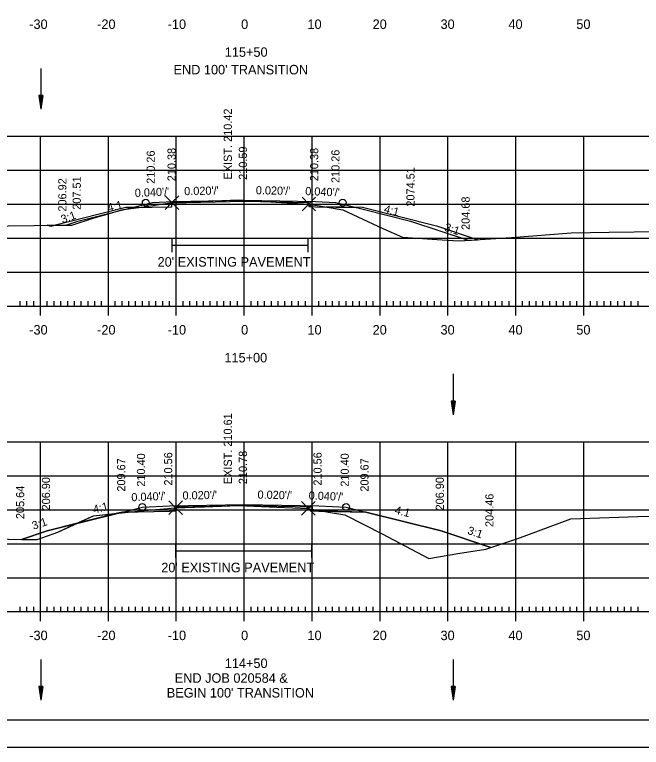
# Model space of a CAD drawing. Extents: x 1312042 to 1371461, y 379929 to 1834241.
# Drawn here: x 1371264.5 to 1371356.8, y 380142.3 to 380250.2 of the extents above; entities that cross this region are included whole.
import ezdxf

# ---------------------------------------------------------------- set-up
doc = ezdxf.new("R2010")
doc.units = 0
for name, color, linetype in [('Default', 7, 'Continuous'), ('R_Alt Surface', 7, 'Continuous'), ('R_Axis', 7, 'Continuous'), ('R_Axis Annot', 7, 'Continuous'), ('R_Border', 7, 'Continuous'), ('R_Exist Surface', 7, 'Continuous'), ('R_Fin Surface', 7, 'Continuous'), ('R_Grid', 7, 'Continuous'), ('R_No Plot', 7, 'Continuous'), ('R_Water Annot', 7, 'Continuous'), ('R_Xsect Elev', 7, 'Continuous'), ('R_Xsect Slope', 7, 'Continuous')]:
    doc.layers.add(name, color=color, linetype=linetype)

msp = doc.modelspace()

# ---------------------------------------------------------------- linework, layer by layer
at = {"layer": 'Default'}
for p, q in [((1371287.64, 380217.25), (1371287.64, 380215.19)), ((1371307.64, 380217.25), (1371307.64, 380215.19)), ((1371287.64, 380216.22), (1371307.64, 380216.22)), ((1371307.72, 380177.67), (1371308.28, 380177.66)), ((1371288.18, 380172.25), (1371288.18, 380170.19)), ((1371308.18, 380172.25), (1371308.18, 380170.19)), ((1371288.18, 380171.22), (1371308.18, 380171.22))]:
    msp.add_line(p, q, dxfattribs=at)
at = {"layer": 'R_Alt Surface'}
for points in [[(1371281.78, 380221.76), (1371287.64, 380221.88), (1371287.64, 380222.46), (1371298.28, 380222.67), (1371307.8, 380222.48), (1371307.8, 380221.9), (1371308.79, 380221.88), (1371314.78, 380221.76)], [(1371280.36, 380176.92), (1371287.29, 380177.06), (1371288.18, 380177.08), (1371288.18, 380177.66), (1371298.28, 380177.86), (1371308.28, 380177.66), (1371308.28, 380177.08), (1371309.29, 380177.06), (1371316.19, 380176.92)]]:
    msp.add_lwpolyline(points, dxfattribs=at)
at = {"layer": 'R_Axis'}
for p, q in [((1371265.28, 380207.25), (1371265.28, 380207.95)), ((1371266.28, 380207.25), (1371266.28, 380207.95)), ((1371267.28, 380207.25), (1371267.28, 380207.95)), ((1371268.28, 380205.85), (1371268.28, 380208.65)), ((1371269.28, 380207.25), (1371269.28, 380207.95)), ((1371270.28, 380207.25), (1371270.28, 380207.95)), ((1371271.28, 380207.25), (1371271.28, 380207.95)), ((1371272.28, 380207.25), (1371272.28, 380207.95)), ((1371273.28, 380207.25), (1371273.28, 380207.95)), ((1371274.28, 380207.25), (1371274.28, 380207.95)), ((1371275.28, 380207.25), (1371275.28, 380207.95)), ((1371276.28, 380207.25), (1371276.28, 380207.95)), ((1371277.28, 380207.25), (1371277.28, 380207.95)), ((1371278.28, 380205.85), (1371278.28, 380208.65)), ((1371279.28, 380207.25), (1371279.28, 380207.95)), ((1371280.28, 380207.25), (1371280.28, 380207.95)), ((1371281.28, 380207.25), (1371281.28, 380207.95)), ((1371282.28, 380207.25), (1371282.28, 380207.95)), ((1371283.28, 380207.25), (1371283.28, 380207.95)), ((1371284.28, 380207.25), (1371284.28, 380207.95)), ((1371285.28, 380207.25), (1371285.28, 380207.95)), ((1371286.28, 380207.25), (1371286.28, 380207.95)), ((1371287.28, 380207.25), (1371287.28, 380207.95)), ((1371288.28, 380205.85), (1371288.28, 380208.65)), ((1371289.28, 380207.25), (1371289.28, 380207.95)), ((1371290.28, 380207.25), (1371290.28, 380207.95)), ((1371291.28, 380207.25), (1371291.28, 380207.95)), ((1371292.28, 380207.25), (1371292.28, 380207.95)), ((1371293.28, 380207.25), (1371293.28, 380207.95)), ((1371294.28, 380207.25), (1371294.28, 380207.95)), ((1371295.28, 380207.25), (1371295.28, 380207.95)), ((1371296.28, 380207.25), (1371296.28, 380207.95)), ((1371297.28, 380207.25), (1371297.28, 380207.95)), ((1371298.28, 380205.85), (1371298.28, 380208.65)), ((1371299.28, 380207.25), (1371299.28, 380207.95)), ((1371300.28, 380207.25), (1371300.28, 380207.95)), ((1371301.28, 380207.25), (1371301.28, 380207.95)), ((1371302.28, 380207.25), (1371302.28, 380207.95)), ((1371303.28, 380207.25), (1371303.28, 380207.95)), ((1371304.28, 380207.25), (1371304.28, 380207.95)), ((1371305.28, 380207.25), (1371305.28, 380207.95)), ((1371306.28, 380207.25), (1371306.28, 380207.95)), ((1371307.28, 380207.25), (1371307.28, 380207.95)), ((1371308.28, 380205.85), (1371308.28, 380208.65)), ((1371309.28, 380207.25), (1371309.28, 380207.95)), ((1371310.28, 380207.25), (1371310.28, 380207.95)), ((1371311.28, 380207.25), (1371311.28, 380207.95)), ((1371312.28, 380207.25), (1371312.28, 380207.95)), ((1371313.28, 380207.25), (1371313.28, 380207.95)), ((1371314.28, 380207.25), (1371314.28, 380207.95)), ((1371315.28, 380207.25), (1371315.28, 380207.95)), ((1371316.28, 380207.25), (1371316.28, 380207.95)), ((1371317.28, 380207.25), (1371317.28, 380207.95)), ((1371318.28, 380205.85), (1371318.28, 380208.65)), ((1371319.28, 380207.25), (1371319.28, 380207.95)), ((1371320.28, 380207.25), (1371320.28, 380207.95)), ((1371321.28, 380207.25), (1371321.28, 380207.95)), ((1371322.28, 380207.25), (1371322.28, 380207.95)), ((1371323.28, 380207.25), (1371323.28, 380207.95)), ((1371324.28, 380207.25), (1371324.28, 380207.95)), ((1371325.28, 380207.25), (1371325.28, 380207.95)), ((1371326.28, 380207.25), (1371326.28, 380207.95)), ((1371327.28, 380207.25), (1371327.28, 380207.95)), ((1371328.28, 380205.85), (1371328.28, 380208.65)), ((1371329.28, 380207.25), (1371329.28, 380207.95)), ((1371330.28, 380207.25), (1371330.28, 380207.95)), ((1371331.28, 380207.25), (1371331.28, 380207.95)), ((1371332.28, 380207.25), (1371332.28, 380207.95)), ((1371333.28, 380207.25), (1371333.28, 380207.95)), ((1371334.28, 380207.25), (1371334.28, 380207.95)), ((1371335.28, 380207.25), (1371335.28, 380207.95)), ((1371336.28, 380207.25), (1371336.28, 380207.95)), ((1371337.28, 380207.25), (1371337.28, 380207.95)), ((1371338.28, 380205.85), (1371338.28, 380208.65)), ((1371339.28, 380207.25), (1371339.28, 380207.95)), ((1371340.28, 380207.25), (1371340.28, 380207.95)), ((1371341.28, 380207.25), (1371341.28, 380207.95)), ((1371342.28, 380207.25), (1371342.28, 380207.95)), ((1371343.28, 380207.25), (1371343.28, 380207.95)), ((1371344.28, 380207.25), (1371344.28, 380207.95)), ((1371345.28, 380207.25), (1371345.28, 380207.95)), ((1371346.28, 380207.25), (1371346.28, 380207.95)), ((1371347.28, 380207.25), (1371347.28, 380207.95)), ((1371348.28, 380205.85), (1371348.28, 380208.65)), ((1371349.28, 380207.25), (1371349.28, 380207.95)), ((1371350.28, 380207.25), (1371350.28, 380207.95)), ((1371351.28, 380207.25), (1371351.28, 380207.95)), ((1371352.28, 380207.25), (1371352.28, 380207.95)), ((1371353.28, 380207.25), (1371353.28, 380207.95)), ((1371354.28, 380207.25), (1371354.28, 380207.95)), ((1371355.28, 380207.25), (1371355.28, 380207.95)), ((1371356.28, 380207.25), (1371356.28, 380207.95)), ((1371158.28, 380207.25), (1371438.28, 380207.25)), ((1371268.28, 380160.85), (1371268.28, 380163.65)), ((1371278.28, 380160.85), (1371278.28, 380163.65)), ((1371288.28, 380160.85), (1371288.28, 380163.65)), ((1371298.28, 380160.85), (1371298.28, 380163.65)), ((1371308.28, 380160.85), (1371308.28, 380163.65)), ((1371318.28, 380160.85), (1371318.28, 380163.65)), ((1371328.28, 380160.85), (1371328.28, 380163.65)), ((1371338.28, 380160.85), (1371338.28, 380163.65)), ((1371348.28, 380160.85), (1371348.28, 380163.65)), ((1371265.28, 380162.25), (1371265.28, 380162.95)), ((1371266.28, 380162.25), (1371266.28, 380162.95)), ((1371267.28, 380162.25), (1371267.28, 380162.95)), ((1371269.28, 380162.25), (1371269.28, 380162.95)), ((1371270.28, 380162.25), (1371270.28, 380162.95)), ((1371271.28, 380162.25), (1371271.28, 380162.95)), ((1371272.28, 380162.25), (1371272.28, 380162.95)), ((1371273.28, 380162.25), (1371273.28, 380162.95)), ((1371274.28, 380162.25), (1371274.28, 380162.95)), ((1371275.28, 380162.25), (1371275.28, 380162.95)), ((1371276.28, 380162.25), (1371276.28, 380162.95)), ((1371277.28, 380162.25), (1371277.28, 380162.95)), ((1371279.28, 380162.25), (1371279.28, 380162.95)), ((1371280.28, 380162.25), (1371280.28, 380162.95)), ((1371281.28, 380162.25), (1371281.28, 380162.95)), ((1371282.28, 380162.25), (1371282.28, 380162.95)), ((1371283.28, 380162.25), (1371283.28, 380162.95)), ((1371284.28, 380162.25), (1371284.28, 380162.95)), ((1371285.28, 380162.25), (1371285.28, 380162.95)), ((1371286.28, 380162.25), (1371286.28, 380162.95)), ((1371287.28, 380162.25), (1371287.28, 380162.95)), ((1371289.28, 380162.25), (1371289.28, 380162.95)), ((1371290.28, 380162.25), (1371290.28, 380162.95)), ((1371291.28, 380162.25), (1371291.28, 380162.95)), ((1371292.28, 380162.25), (1371292.28, 380162.95)), ((1371293.28, 380162.25), (1371293.28, 380162.95)), ((1371294.28, 380162.25), (1371294.28, 380162.95)), ((1371295.28, 380162.25), (1371295.28, 380162.95)), ((1371296.28, 380162.25), (1371296.28, 380162.95)), ((1371297.28, 380162.25), (1371297.28, 380162.95)), ((1371299.28, 380162.25), (1371299.28, 380162.95)), ((1371300.28, 380162.25), (1371300.28, 380162.95)), ((1371301.28, 380162.25), (1371301.28, 380162.95)), ((1371302.28, 380162.25), (1371302.28, 380162.95)), ((1371303.28, 380162.25), (1371303.28, 380162.95)), ((1371304.28, 380162.25), (1371304.28, 380162.95)), ((1371305.28, 380162.25), (1371305.28, 380162.95)), ((1371306.28, 380162.25), (1371306.28, 380162.95)), ((1371307.28, 380162.25), (1371307.28, 380162.95)), ((1371309.28, 380162.25), (1371309.28, 380162.95)), ((1371310.28, 380162.25), (1371310.28, 380162.95)), ((1371311.28, 380162.25), (1371311.28, 380162.95)), ((1371312.28, 380162.25), (1371312.28, 380162.95)), ((1371313.28, 380162.25), (1371313.28, 380162.95)), ((1371314.28, 380162.25), (1371314.28, 380162.95)), ((1371315.28, 380162.25), (1371315.28, 380162.95)), ((1371316.28, 380162.25), (1371316.28, 380162.95)), ((1371317.28, 380162.25), (1371317.28, 380162.95)), ((1371319.28, 380162.25), (1371319.28, 380162.95)), ((1371320.28, 380162.25), (1371320.28, 380162.95)), ((1371321.28, 380162.25), (1371321.28, 380162.95)), ((1371322.28, 380162.25), (1371322.28, 380162.95)), ((1371323.28, 380162.25), (1371323.28, 380162.95)), ((1371324.28, 380162.25), (1371324.28, 380162.95)), ((1371325.28, 380162.25), (1371325.28, 380162.95)), ((1371326.28, 380162.25), (1371326.28, 380162.95)), ((1371327.28, 380162.25), (1371327.28, 380162.95)), ((1371329.28, 380162.25), (1371329.28, 380162.95)), ((1371330.28, 380162.25), (1371330.28, 380162.95)), ((1371331.28, 380162.25), (1371331.28, 380162.95)), ((1371332.28, 380162.25), (1371332.28, 380162.95)), ((1371333.28, 380162.25), (1371333.28, 380162.95)), ((1371334.28, 380162.25), (1371334.28, 380162.95)), ((1371335.28, 380162.25), (1371335.28, 380162.95)), ((1371336.28, 380162.25), (1371336.28, 380162.95)), ((1371337.28, 380162.25), (1371337.28, 380162.95)), ((1371339.28, 380162.25), (1371339.28, 380162.95)), ((1371340.28, 380162.25), (1371340.28, 380162.95)), ((1371341.28, 380162.25), (1371341.28, 380162.95)), ((1371342.28, 380162.25), (1371342.28, 380162.95)), ((1371343.28, 380162.25), (1371343.28, 380162.95)), ((1371344.28, 380162.25), (1371344.28, 380162.95)), ((1371345.28, 380162.25), (1371345.28, 380162.95)), ((1371346.28, 380162.25), (1371346.28, 380162.95)), ((1371347.28, 380162.25), (1371347.28, 380162.95)), ((1371349.28, 380162.25), (1371349.28, 380162.95)), ((1371350.28, 380162.25), (1371350.28, 380162.95)), ((1371351.28, 380162.25), (1371351.28, 380162.95)), ((1371352.28, 380162.25), (1371352.28, 380162.95)), ((1371353.28, 380162.25), (1371353.28, 380162.95)), ((1371354.28, 380162.25), (1371354.28, 380162.95)), ((1371355.28, 380162.25), (1371355.28, 380162.95)), ((1371356.28, 380162.25), (1371356.28, 380162.95)), ((1371158.28, 380162.25), (1371438.28, 380162.25))]:
    msp.add_line(p, q, dxfattribs=at)
at = {"layer": 'R_Border'}
msp.add_line((1371456.46, 380146.25), (1371140.28, 380146.25), dxfattribs=at)
at = {"layer": 'R_Exist Surface'}
for points in [[(1371255.66, 380218.96), (1371267.37, 380219.11), (1371272.89, 380219.18), (1371276.02, 380220.17), (1371280.44, 380221.48), (1371284.24, 380221.97), (1371287.64, 380222.48), (1371292.49, 380222.67), (1371297.49, 380222.87), (1371302.99, 380222.55), (1371307.8, 380222.26), (1371309.92, 380221.93), (1371312.78, 380221.44), (1371318.71, 380218.65), (1371321.6, 380217.4), (1371328.19, 380216.94), (1371329.94, 380216.86), (1371337.65, 380217.32), (1371346.44, 380218.02), (1371352.03, 380218.14), (1371366.76, 380218.33)], [(1371258.75, 380173), (1371265.98, 380172.87), (1371267.8, 380172.89), (1371270.81, 380173.96), (1371276.06, 380176.37), (1371283.52, 380177.13), (1371288.18, 380177.54), (1371292.41, 380177.7), (1371297.44, 380177.88), (1371303.07, 380177.63), (1371307.72, 380177.45), (1371310.98, 380176.87), (1371313.11, 380176.51), (1371318.58, 380173.69), (1371325.49, 380170.08), (1371329.74, 380170.82), (1371333.85, 380171.47), (1371338.57, 380173.02), (1371346.36, 380175.92), (1371356.23, 380176.24), (1371361.36, 380176.42)]]:
    msp.add_lwpolyline(points, dxfattribs=at)
at = {"layer": 'R_Fin Surface'}
for points in [[(1371272, 380219.17), (1371273.78, 380219.76), (1371280.58, 380221.46), (1371284.78, 380222.51), (1371287.78, 380222.63), (1371298.28, 380222.84), (1371308.78, 380222.63), (1371311.78, 380222.51), (1371316, 380221.46), (1371322.78, 380219.76), (1371331.25, 380216.94)], [(1371265.48, 380172.88), (1371269.28, 380174.15), (1371280.36, 380176.92), (1371283.28, 380177.65), (1371287.28, 380177.81), (1371298.28, 380178.03), (1371309.28, 380177.81), (1371313.28, 380177.65), (1371316.19, 380176.92), (1371327.28, 380174.15), (1371334.59, 380171.71)]]:
    msp.add_lwpolyline(points, dxfattribs=at)
at = {"layer": 'R_Grid'}
for p, q in [((1371158.28, 380232.25), (1371438.28, 380232.25)), ((1371268.28, 380207.25), (1371268.28, 380232.25)), ((1371278.28, 380207.25), (1371278.28, 380232.25)), ((1371288.28, 380207.25), (1371288.28, 380232.25)), ((1371298.28, 380207.25), (1371298.28, 380232.25)), ((1371308.28, 380207.25), (1371308.28, 380232.25)), ((1371318.28, 380207.25), (1371318.28, 380232.25)), ((1371328.28, 380207.25), (1371328.28, 380232.25)), ((1371338.28, 380207.25), (1371338.28, 380232.25)), ((1371348.28, 380207.25), (1371348.28, 380232.25)), ((1371158.28, 380227.25), (1371438.28, 380227.25)), ((1371158.28, 380222.25), (1371438.28, 380222.25)), ((1371158.28, 380217.25), (1371438.28, 380217.25)), ((1371158.28, 380212.25), (1371438.28, 380212.25)), ((1371158.28, 380207.25), (1371438.28, 380207.25)), ((1371158.28, 380187.25), (1371438.28, 380187.25)), ((1371268.28, 380162.25), (1371268.28, 380187.25)), ((1371278.28, 380162.25), (1371278.28, 380187.25)), ((1371288.28, 380162.25), (1371288.28, 380187.25)), ((1371298.28, 380162.25), (1371298.28, 380187.25)), ((1371308.28, 380162.25), (1371308.28, 380187.25)), ((1371318.28, 380162.25), (1371318.28, 380187.25)), ((1371328.28, 380162.25), (1371328.28, 380187.25)), ((1371338.28, 380162.25), (1371338.28, 380187.25)), ((1371348.28, 380162.25), (1371348.28, 380187.25)), ((1371158.28, 380182.25), (1371438.28, 380182.25)), ((1371158.28, 380177.25), (1371438.28, 380177.25)), ((1371158.28, 380172.25), (1371438.28, 380172.25)), ((1371158.28, 380167.25), (1371438.28, 380167.25)), ((1371158.28, 380162.25), (1371438.28, 380162.25))]:
    msp.add_line(p, q, dxfattribs=at)
at = {"layer": 'R_No Plot'}
msp.add_line((1371127.88, 380142.27), (1371461.21, 380142.27), dxfattribs=at)
for points in [[(1371127.87, 380355.6), (1371461.21, 380355.6), (1371461.21, 380142.26), (1371127.87, 380142.26)], [(1371374.2, 380351.71), (1371374.2, 380341.83), (1371409.93, 380341.83), (1371409.93, 380338.91), (1371433.13, 380338.91), (1371433.13, 380314.57), (1371456.46, 380314.57), (1371456.46, 380146.25), (1371140.28, 380146.25), (1371140.28, 380351.71)], [(1371270.49, 380219.15), (1371272.89, 380219.18), (1371276.02, 380220.17), (1371280.44, 380221.48), (1371282.75, 380221.78), (1371280.86, 380221.74)], [(1371310.37, 380221.85), (1371312.78, 380221.44), (1371318.71, 380218.65), (1371321.6, 380217.4), (1371328.19, 380216.94), (1371329.94, 380216.86), (1371332.64, 380217.02), (1371326.78, 380218.97), (1371315.69, 380221.74)], [(1371269.28, 380219.14), (1371270.49, 380219.15), (1371269.78, 380218.97)], [(1371273.55, 380175.22), (1371276.06, 380176.37), (1371279.61, 380176.73)], [(1371279.61, 380176.73), (1371281.75, 380176.95), (1371280.36, 380176.92)], [(1371310, 380177.04), (1371310.98, 380176.87), (1371313.11, 380176.51), (1371318.58, 380173.69), (1371325.49, 380170.08), (1371329.74, 380170.82), (1371333.85, 380171.47), (1371334.59, 380171.71), (1371327.28, 380174.15), (1371316.19, 380176.92)], [(1371265.48, 380172.88), (1371265.98, 380172.87), (1371267.8, 380172.89), (1371270.81, 380173.96), (1371273.55, 380175.22), (1371269.28, 380174.15)]]:
    msp.add_lwpolyline(points, close=True, dxfattribs=at)
for points in [[(1371287.64, 380222.48), (1371286.64, 380223.48), (1371287.64, 380222.48), (1371286.64, 380221.48), (1371287.64, 380222.48), (1371288.64, 380221.48), (1371287.64, 380222.48), (1371288.64, 380223.48)], [(1371307.8, 380222.26), (1371306.8, 380223.26), (1371307.8, 380222.26), (1371306.8, 380221.26), (1371307.8, 380222.26), (1371308.8, 380221.26), (1371307.8, 380222.26), (1371308.8, 380223.26)], [(1371288.18, 380177.54), (1371287.18, 380178.54), (1371288.18, 380177.54), (1371287.18, 380176.54), (1371288.18, 380177.54), (1371289.18, 380176.54), (1371288.18, 380177.54), (1371289.18, 380178.54)], [(1371307.72, 380177.45), (1371306.72, 380178.45), (1371307.72, 380177.45), (1371306.72, 380176.45), (1371307.72, 380177.45), (1371308.72, 380176.45), (1371307.72, 380177.45), (1371308.72, 380178.45)]]:
    msp.add_lwpolyline(points, dxfattribs=at)
for centre in [(1371283.78, 380222.47), (1371312.78, 380222.47), (1371283.28, 380177.65), (1371313.28, 380177.65)]:
    msp.add_circle(centre, 0.5, dxfattribs=at)
at = {"layer": 'R_Water Annot'}
for p, q in [((1371268.34, 380242.25), (1371268.34, 380236.25)), ((1371268.04, 380238.25), (1371268.34, 380236.25)), ((1371268.64, 380238.25), (1371268.04, 380238.25)), ((1371268.09, 380238.25), (1371268.34, 380236.59)), ((1371268.14, 380238.25), (1371268.34, 380236.93)), ((1371268.19, 380238.25), (1371268.34, 380237.26)), ((1371268.25, 380238.25), (1371268.34, 380237.6)), ((1371268.3, 380238.25), (1371268.34, 380237.94)), ((1371268.64, 380238.25), (1371268.34, 380236.25)), ((1371268.44, 380238.25), (1371268.34, 380237.6)), ((1371268.54, 380238.25), (1371268.34, 380236.93)), ((1371268.59, 380238.25), (1371268.34, 380236.59)), ((1371268.49, 380238.25), (1371268.34, 380237.26)), ((1371268.39, 380238.25), (1371268.34, 380237.94)), ((1371329.05, 380197.25), (1371329.05, 380191.25)), ((1371328.75, 380193.25), (1371329.05, 380191.25)), ((1371329.35, 380193.25), (1371328.75, 380193.25)), ((1371328.8, 380193.25), (1371329.05, 380191.59)), ((1371328.85, 380193.25), (1371329.05, 380191.93)), ((1371328.9, 380193.25), (1371329.05, 380192.26)), ((1371328.95, 380193.25), (1371329.05, 380192.6)), ((1371329, 380193.25), (1371329.05, 380192.94)), ((1371329.35, 380193.25), (1371329.05, 380191.25)), ((1371329.15, 380193.25), (1371329.05, 380192.6)), ((1371329.25, 380193.25), (1371329.05, 380191.93)), ((1371329.3, 380193.25), (1371329.05, 380191.59)), ((1371329.2, 380193.25), (1371329.05, 380192.26)), ((1371329.1, 380193.25), (1371329.05, 380192.94)), ((1371268.34, 380155.2), (1371268.34, 380149.2)), ((1371329.05, 380155.2), (1371329.05, 380149.2)), ((1371268.04, 380151.2), (1371268.34, 380149.2)), ((1371268.64, 380151.2), (1371268.04, 380151.2)), ((1371268.09, 380151.2), (1371268.34, 380149.53)), ((1371268.14, 380151.2), (1371268.34, 380149.87)), ((1371268.19, 380151.2), (1371268.34, 380150.21)), ((1371268.25, 380151.2), (1371268.34, 380150.55)), ((1371268.3, 380151.2), (1371268.34, 380150.88)), ((1371268.64, 380151.2), (1371268.34, 380149.2)), ((1371268.44, 380151.2), (1371268.34, 380150.55)), ((1371268.54, 380151.2), (1371268.34, 380149.87)), ((1371268.59, 380151.2), (1371268.34, 380149.53)), ((1371268.49, 380151.2), (1371268.34, 380150.21)), ((1371268.39, 380151.2), (1371268.34, 380150.88)), ((1371328.75, 380151.2), (1371329.05, 380149.2)), ((1371329.35, 380151.2), (1371328.75, 380151.2)), ((1371328.8, 380151.2), (1371329.05, 380149.53)), ((1371328.85, 380151.2), (1371329.05, 380149.87)), ((1371328.9, 380151.2), (1371329.05, 380150.21)), ((1371328.95, 380151.2), (1371329.05, 380150.55)), ((1371329, 380151.2), (1371329.05, 380150.88)), ((1371329.35, 380151.2), (1371329.05, 380149.2)), ((1371329.15, 380151.2), (1371329.05, 380150.55)), ((1371329.25, 380151.2), (1371329.05, 380149.87)), ((1371329.3, 380151.2), (1371329.05, 380149.53)), ((1371329.2, 380151.2), (1371329.05, 380150.21)), ((1371329.1, 380151.2), (1371329.05, 380150.88))]:
    msp.add_line(p, q, dxfattribs=at)

# ---------------------------------------------------------------- texts
at = {"layer": 'R_Axis Annot'}
for s, p in [('-30', (1371266.62, 380248.05)), ('-20', (1371276.62, 380248.05)), ('-10', (1371287.01, 380248.05)), ('0', (1371297.82, 380248.05)), ('10', (1371307.59, 380248.05)), ('20', (1371317.19, 380248.05)), ('30', (1371327.19, 380248.05)), ('40', (1371337.19, 380248.05)), ('50', (1371347.19, 380248.05)), ('115+50', (1371295.42, 380243.95)), ("END 100' TRANSITION", (1371287.87, 380241.36)), ("20' EXISTING PAVEMENT", (1371285.52, 380213.05)), ('-30', (1371266.62, 380203.05)), ('-20', (1371276.62, 380203.05)), ('-10', (1371287.01, 380203.05)), ('0', (1371297.82, 380203.05)), ('10', (1371307.59, 380203.05)), ('20', (1371317.19, 380203.05)), ('30', (1371327.19, 380203.05)), ('40', (1371337.19, 380203.05)), ('50', (1371347.19, 380203.05)), ('115+00', (1371295.36, 380198.95)), ("20' EXISTING PAVEMENT", (1371286.06, 380168.05)), ('-30', (1371266.62, 380158.05)), ('-20', (1371276.62, 380158.05)), ('-10', (1371287.01, 380158.05)), ('0', (1371297.82, 380158.05)), ('10', (1371307.59, 380158.05)), ('20', (1371317.19, 380158.05)), ('30', (1371327.19, 380158.05)), ('40', (1371337.19, 380158.05)), ('50', (1371347.19, 380158.05)), ('114+50', (1371295.42, 380153.95)), ('END JOB 020584 &', (1371288.05, 380151.77)), ("BEGIN 100' TRANSITION", (1371286.87, 380149.6))]:
    msp.add_text(s, height=1.4, dxfattribs=at).set_placement(p)
at = {"layer": 'R_Xsect Elev'}
for s, p in [('EXIST. 210.42', (1371296.46, 380225.89)), ('210.38', (1371288.18, 380225.63)), ('210.59', (1371298.68, 380225.84)), ('210.38', (1371309.18, 380225.63)), ('210.26', (1371285.11, 380225.25)), ('210.26', (1371312.31, 380225.37)), ('2074.51', (1371323.36, 380221.89)), ('206.92', (1371272.09, 380221.16)), ('207.51', (1371274.21, 380221.43)), ('204.68', (1371331.48, 380218.46)), ('EXIST. 210.61', (1371296.46, 380181.02)), ('210.40', (1371283.68, 380180.65)), ('210.56', (1371287.68, 380180.81)), ('210.78', (1371298.68, 380181.03)), ('210.56', (1371309.68, 380180.81)), ('210.40', (1371313.68, 380180.65)), ('209.67', (1371280.76, 380179.92)), ('209.67', (1371316.59, 380179.92)), ('206.90', (1371269.68, 380177.15)), ('206.90', (1371327.68, 380177.15)), ('205.64', (1371265.88, 380175.88)), ('204.46', (1371334.99, 380174.71))]:
    msp.add_text(s, height=1.2, rotation=90, dxfattribs=at).set_placement(p)
at = {"layer": 'R_Xsect Slope'}
for s, rotation, p in [("0.020'/'", 1.1458, (1371289.45, 380223.57)), ("0.020'/'", 358.8542, (1371299.98, 380223.71)), ("0.040'/'", 2.2906, (1371282.18, 380223.31)), ("0.040'/'", 357.7094, (1371307.25, 380223.59)), ('4:1', 14.0362, (1371278.29, 380221.1)), ('4:1', 345.9638, (1371318.77, 380221.02)), ('3:1', 19.2426, (1371271.52, 380219.41)), ('3:1', 341.5651, (1371327.66, 380218.37)), ("0.040'/'", 2.2906, (1371281.68, 380178.49)), ("0.020'/'", 1.1458, (1371289.2, 380178.75)), ("0.020'/'", 358.8542, (1371300.23, 380178.89)), ("0.040'/'", 357.7094, (1371307.75, 380178.77)), ('4:1', 14.0362, (1371276.18, 380176.69)), ('4:1', 345.9638, (1371320.37, 380176.69)), ('3:1', 18.4349, (1371267.25, 380174.3)), ('3:1', 341.5651, (1371331.06, 380173.71))]:
    msp.add_text(s, height=1.2, rotation=rotation, dxfattribs=at).set_placement(p)

doc.saveas('drawing.dxf')
